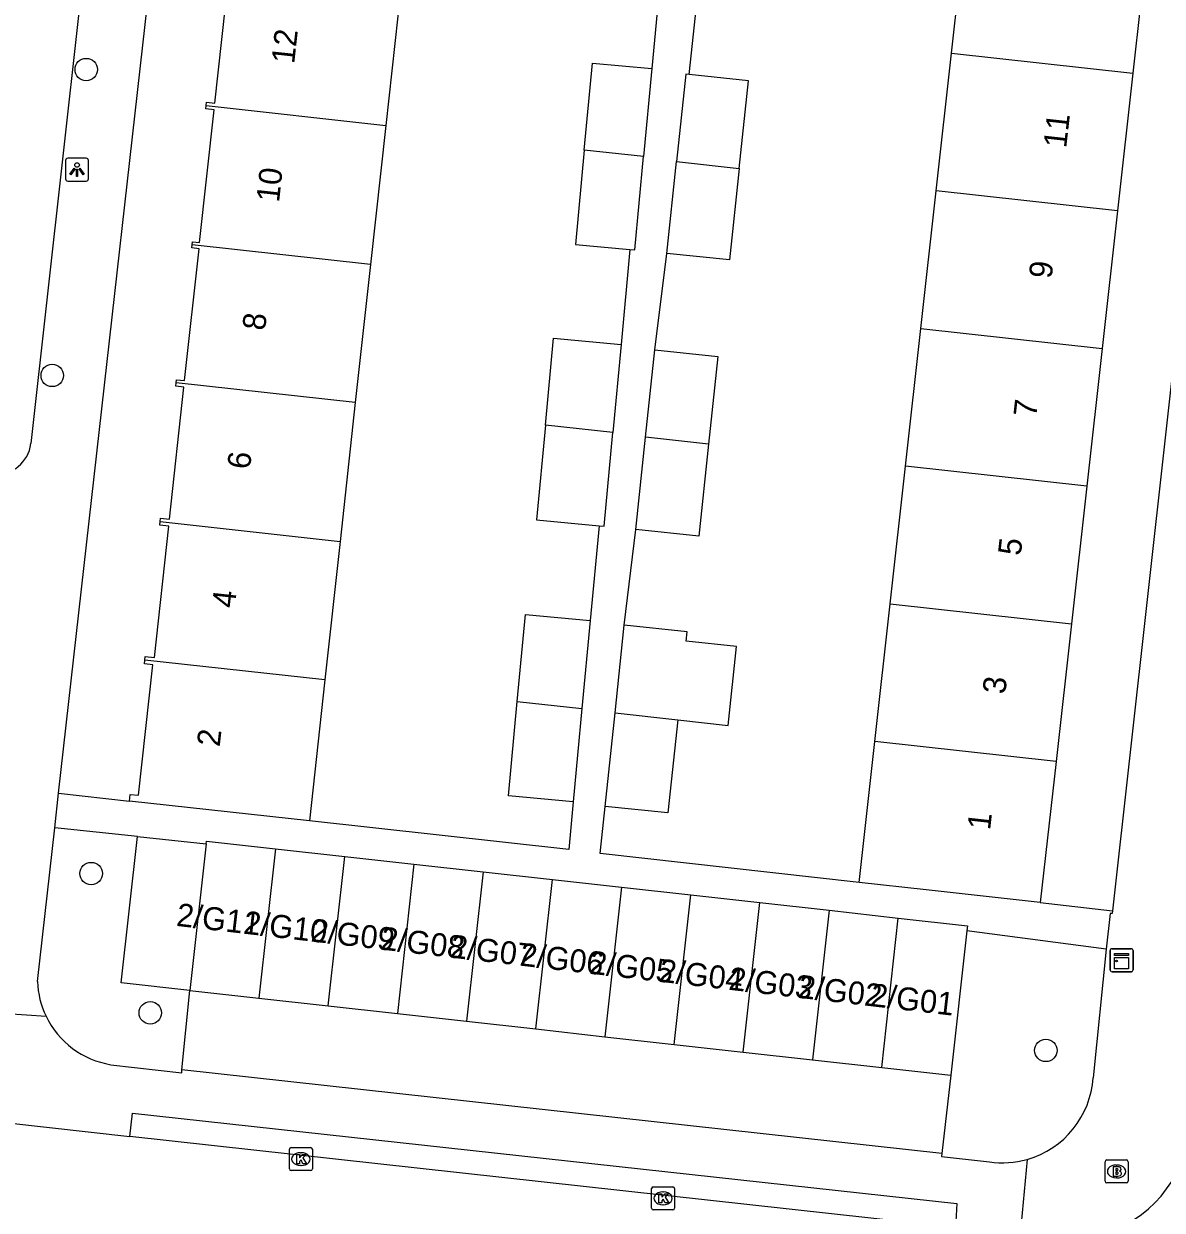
# Model space of a CAD drawing. Extents: x 161928 to 163055, y 386475 to 387428.
# Drawn here: x 162121.6 to 162171.2, y 386544.6 to 386596.2 of the extents above; entities that cross this region are included whole.
import ezdxf

# ---------------------------------------------------------------- set-up
doc = ezdxf.new("R2010")
doc.units = 0
for name, color, linetype in [('IMGEO_Boom', 7, 'Continuous'), ('IMGEO_Brandkraan', 7, 'Continuous'), ('IMGEO_Groenvoorziening', 7, 'Continuous'), ('IMGEO_Kast', 7, 'Continuous'), ('IMGEO_Kolk', 7, 'Continuous'), ('IMGEO_Lichtpunt', 7, 'Continuous'), ('IMGEO_Pand', 7, 'Continuous'), ('IMGEO_Pand_nummerreeks', 7, 'Continuous'), ('IMGEO_Rijbaan_lokaal_open', 7, 'Continuous'), ('IMGEO_Voetpad_gesloten', 7, 'Continuous'), ('IMGEO_Voetpad_open', 7, 'Continuous')]:
    doc.layers.add(name, color=color, linetype=linetype)

msp = doc.modelspace()

# ---------------------------------------------------------------- linework, layer by layer
at = {"layer": 'IMGEO_Boom'}
for centre in [(162124.314, 386594.21), (162122.834, 386580.895), (162124.531, 386559.208), (162127.103, 386553.146), (162166.086, 386551.512)]:
    msp.add_circle(centre, 0.489, dxfattribs=at)
at = {"layer": 'IMGEO_Brandkraan'}
for p, q in [((162168.666, 386545.815), (162168.666, 386546.667)), ((162168.741, 386546.741), (162169.593, 386546.741)), ((162169.154, 386546.521), (162169.179, 386546.521)), ((162169.667, 386546.667), (162169.667, 386545.815)), ((162169.177, 386545.961), (162169.152, 386545.961)), ((162169.593, 386545.741), (162168.741, 386545.741))]:
    msp.add_line(p, q, dxfattribs=at)
for points in [[(162168.666, 386545.815), (162168.666, 386546.667)], [(162168.741, 386546.741), (162169.593, 386546.741)], [(162169.014, 386546.441), (162169.014, 386546.041), (162169.227, 386546.041)], [(162169.245, 386546.441), (162169.014, 386546.441)], [(162169.193, 386546.36), (162169.139, 386546.36), (162169.139, 386546.284)], [(162169.139, 386546.284), (162169.192, 386546.284)], [(162169.667, 386546.667), (162169.667, 386545.815)], [(162169.201, 386546.208), (162169.139, 386546.208), (162169.139, 386546.127)], [(162169.139, 386546.127), (162169.201, 386546.127)], [(162169.593, 386545.741), (162168.741, 386545.741)]]:
    msp.add_lwpolyline(points, dxfattribs=at)
for centre, radius, start, end in [((162168.743, 386546.665), 0.0765, 91.552, 178.448), ((162168.743, 386546.665), 0.0765, 91.552, 178.448), ((162169.194, 386546.322), 0.0379, 267.8285, 90.9355), ((162169.249, 386546.296), 0.145, 59.4692, 91.5367), ((162169.274, 386546.343), 0.0922, 285.5137, 58.1501), ((162169.591, 386546.665), 0.0765, 1.552, 88.448), ((162169.591, 386546.665), 0.0765, 1.552, 88.448), ((162168.743, 386545.817), 0.0765, 181.552, 268.448), ((162168.743, 386545.817), 0.0765, 181.552, 268.448), ((162169.202, 386546.167), 0.0404, 269.8759, 90.5077), ((162169.233, 386546.292), 0.251, 268.6676, 293.5347), ((162169.279, 386546.151), 0.105, 301.3115, 78.989), ((162169.591, 386545.817), 0.0765, 271.552, 358.448), ((162169.591, 386545.817), 0.0765, 271.552, 358.448)]:
    msp.add_arc(centre, radius, start, end, dxfattribs=at)
for centre, major_axis, ratio, start_param, end_param in [((162169.153, 386546.241), (-0.387, 0.002), 0.722429, 4.712389, 7.853982), ((162169.178, 386546.241), (-0.39, 0.002), 0.717154, 1.570796, 4.712389)]:
    msp.add_ellipse(centre, major_axis=major_axis, ratio=ratio, start_param=start_param, end_param=end_param, dxfattribs=at)
at = {"layer": 'IMGEO_Groenvoorziening'}
msp.add_lwpolyline([(162128.822, 386554.12), (162125.84, 386554.452), (162126.549, 386560.818)], dxfattribs=at)
at = {"layer": 'IMGEO_Kast'}
for p, q in [((162168.886, 386555.013), (162168.886, 386555.854)), ((162168.886, 386555.854), (162168.886, 386555.013)), ((162168.961, 386555.938), (162169.802, 386555.938)), ((162169.802, 386555.938), (162168.961, 386555.938)), ((162169.886, 386555.863), (162169.886, 386555.022)), ((162169.886, 386555.022), (162169.886, 386555.863)), ((162169.811, 386554.938), (162168.97, 386554.938)), ((162168.97, 386554.938), (162169.811, 386554.938))]:
    msp.add_line(p, q, dxfattribs=at)
for points in [[(162169.081, 386555.728), (162169.681, 386555.728), (162169.681, 386555.643), (162169.081, 386555.643), (162169.081, 386555.728)], [(162169.081, 386555.553), (162169.681, 386555.553), (162169.681, 386555.064), (162169.081, 386555.064), (162169.081, 386555.553)]]:
    msp.add_lwpolyline(points, dxfattribs=at)
msp.add_circle((162169.165, 386555.402), 0.0377, dxfattribs=at)
for centre, start, end in [((162168.964, 386555.86), 92.4484, 184.2845), ((162168.964, 386555.86), 92.4484, 184.2845), ((162169.808, 386555.86), 2.4484, 94.2845), ((162169.808, 386555.86), 2.4484, 94.2845), ((162168.964, 386555.016), 182.4484, 274.2845), ((162168.964, 386555.016), 182.4484, 274.2845), ((162169.808, 386555.016), 272.4484, 4.2845), ((162169.808, 386555.016), 272.4484, 4.2845)]:
    msp.add_arc(centre, 0.0779, start, end, dxfattribs=at)
at = {"layer": 'IMGEO_Kolk'}
for p, q in [((162133.156, 386546.353), (162133.156, 386547.205)), ((162133.231, 386547.279), (162134.083, 386547.279)), ((162133.644, 386547.059), (162133.669, 386547.059)), ((162134.157, 386547.205), (162134.157, 386546.353)), ((162134.083, 386546.279), (162133.231, 386546.279)), ((162133.667, 386546.499), (162133.642, 386546.499)), ((162148.924, 386544.644), (162148.924, 386545.496)), ((162148.999, 386545.57), (162149.851, 386545.57)), ((162149.412, 386545.35), (162149.437, 386545.35)), ((162149.925, 386545.496), (162149.925, 386544.644)), ((162149.435, 386544.79), (162149.41, 386544.79)), ((162149.851, 386544.57), (162148.999, 386544.57))]:
    msp.add_line(p, q, dxfattribs=at)
for points in [[(162133.156, 386546.353), (162133.156, 386547.205)], [(162133.231, 386547.279), (162134.083, 386547.279)], [(162133.477, 386546.979), (162133.6, 386546.979), (162133.6, 386546.828), (162133.73, 386546.979), (162133.894, 386546.979), (162133.748, 386546.828), (162133.901, 386546.579), (162133.749, 386546.579), (162133.664, 386546.743), (162133.6, 386546.676), (162133.6, 386546.579), (162133.477, 386546.579), (162133.477, 386546.979)], [(162134.157, 386547.205), (162134.157, 386546.353)], [(162134.083, 386546.279), (162133.231, 386546.279)], [(162148.924, 386544.644), (162148.924, 386545.496)], [(162148.999, 386545.57), (162149.851, 386545.57)], [(162149.245, 386545.27), (162149.368, 386545.27), (162149.368, 386545.119), (162149.498, 386545.27), (162149.662, 386545.27), (162149.516, 386545.119), (162149.669, 386544.87), (162149.517, 386544.87), (162149.432, 386545.034), (162149.368, 386544.967), (162149.368, 386544.87), (162149.245, 386544.87), (162149.245, 386545.27)], [(162149.925, 386545.496), (162149.925, 386544.644)], [(162149.851, 386544.57), (162148.999, 386544.57)]]:
    msp.add_lwpolyline(points, dxfattribs=at)
for centre, start, end in [((162133.233, 386547.203), 91.552, 178.448), ((162133.233, 386547.203), 91.552, 178.448), ((162134.081, 386547.203), 1.552, 88.448), ((162134.081, 386547.203), 1.552, 88.448), ((162133.233, 386546.355), 181.552, 268.448), ((162133.233, 386546.355), 181.552, 268.448), ((162134.081, 386546.355), 271.552, 358.448), ((162134.081, 386546.355), 271.552, 358.448), ((162149.001, 386545.494), 91.552, 178.448), ((162149.001, 386545.494), 91.552, 178.448), ((162149.849, 386545.494), 1.552, 88.448), ((162149.849, 386545.494), 1.552, 88.448), ((162149.001, 386544.646), 181.552, 268.448), ((162149.001, 386544.646), 181.552, 268.448), ((162149.849, 386544.646), 271.552, 358.448), ((162149.849, 386544.646), 271.552, 358.448)]:
    msp.add_arc(centre, 0.0765, start, end, dxfattribs=at)
for centre, major_axis, ratio, start_param, end_param in [((162133.643, 386546.779), (-0.387, 0.002), 0.722429, 4.712389, 7.853982), ((162133.668, 386546.779), (-0.39, 0.002), 0.717154, 1.570796, 4.712389), ((162149.411, 386545.07), (-0.387, 0.002), 0.722429, 4.712389, 7.853982), ((162149.436, 386545.07), (-0.39, 0.002), 0.717154, 1.570796, 4.712389)]:
    msp.add_ellipse(centre, major_axis=major_axis, ratio=ratio, start_param=start_param, end_param=end_param, dxfattribs=at)
at = {"layer": 'IMGEO_Lichtpunt'}
for p, q in [((162123.415, 386590.258), (162123.415, 386589.451)), ((162123.415, 386590.258), (162123.415, 386589.451)), ((162124.317, 386590.353), (162123.509, 386590.353)), ((162124.317, 386590.353), (162123.509, 386590.353)), ((162124.411, 386589.451), (162124.411, 386590.258)), ((162124.411, 386589.451), (162124.411, 386590.258)), ((162123.509, 386589.357), (162124.317, 386589.357)), ((162123.509, 386589.357), (162124.317, 386589.357))]:
    msp.add_line(p, q, dxfattribs=at)
for points in [[(162123.789, 386589.922), (162123.828, 386589.894), (162123.64, 386589.632), (162123.602, 386589.659), (162123.789, 386589.922)], [(162123.891, 386589.874), (162123.938, 386589.874), (162123.938, 386589.552), (162123.891, 386589.552), (162123.891, 386589.874)], [(162124.001, 386589.894), (162124.039, 386589.921), (162124.226, 386589.659), (162124.187, 386589.631), (162124.001, 386589.894)]]:
    msp.add_lwpolyline(points, dxfattribs=at)
msp.add_circle((162123.914, 386590.056), 0.0994, dxfattribs=at)
for centre, start, end in [((162123.509, 386590.258), 90, 180), ((162123.509, 386590.258), 90, 180), ((162124.317, 386590.258), 0, 90), ((162124.317, 386590.258), 0, 90), ((162123.509, 386589.451), 180, 270), ((162123.509, 386589.451), 180, 270), ((162124.317, 386589.451), 270, 0), ((162124.317, 386589.451), 270, 360)]:
    msp.add_arc(centre, 0.0946, start, end, dxfattribs=at)
at = {"layer": 'IMGEO_Pand'}
for points in [[(162161.984, 386594.927), (162162.653, 386600.92)], [(162170.545, 386600.04), (162169.876, 386594.047)], [(162129.534, 386592.64), (162129.55, 386592.784), (162129.918, 386592.744), (162130.542, 386598.439), (162130.194, 386598.477), (162130.208, 386598.602)], [(162138.002, 386597.745), (162137.349, 386591.781)], [(162161.315, 386588.934), (162161.984, 386594.927)], [(162161.984, 386594.927), (162169.876, 386594.047)], [(162145.991, 386590.704), (162146.346, 386594.494), (162148.936, 386594.251)], [(162148.936, 386594.251), (162148.577, 386590.42)], [(162150.564, 386593.998), (162150.411, 386594.014), (162150.009, 386590.204)], [(162152.744, 386589.898), (162153.148, 386593.725), (162150.564, 386593.998)], [(162169.876, 386594.047), (162169.207, 386588.054)], [(162128.923, 386586.578), (162128.937, 386586.711), (162129.251, 386586.676), (162129.884, 386592.457), (162129.519, 386592.497), (162129.534, 386592.64)], [(162129.534, 386592.64), (162137.349, 386591.781)], [(162137.349, 386591.781), (162136.686, 386585.724)], [(162145.991, 386590.704), (162145.607, 386586.601), (162147.982, 386586.379)], [(162148.577, 386590.42), (162145.991, 386590.704)], [(162147.982, 386586.379), (162148.197, 386586.359), (162148.577, 386590.42)], [(162149.587, 386586.21), (162150.009, 386590.204)], [(162150.009, 386590.204), (162152.744, 386589.898)], [(162152.744, 386589.898), (162152.324, 386585.921), (162149.587, 386586.21)], [(162160.646, 386582.942), (162161.315, 386588.934)], [(162169.207, 386588.054), (162161.315, 386588.934)], [(162169.207, 386588.054), (162168.539, 386582.062)], [(162128.229, 386580.57), (162128.244, 386580.71), (162128.597, 386580.671), (162129.225, 386586.409), (162128.908, 386586.444), (162128.923, 386586.578)], [(162136.686, 386585.724), (162128.923, 386586.578)], [(162136.686, 386585.724), (162136.028, 386579.713)], [(162144.305, 386578.728), (162144.659, 386582.512), (162147.595, 386582.237)], [(162159.977, 386576.949), (162160.646, 386582.942)], [(162160.646, 386582.942), (162168.539, 386582.062)], [(162147.595, 386582.237), (162147.236, 386578.406)], [(162148.662, 386578.206), (162149.064, 386582.016)], [(162149.064, 386582.016), (162151.809, 386581.726), (162151.405, 386577.9)], [(162168.539, 386582.062), (162167.87, 386576.069)], [(162127.529, 386574.53), (162127.546, 386574.684), (162127.94, 386574.641), (162128.569, 386580.391), (162128.214, 386580.43), (162128.229, 386580.57)], [(162136.028, 386579.713), (162128.229, 386580.57)], [(162136.028, 386579.713), (162135.366, 386573.668)], [(162144.305, 386578.728), (162143.919, 386574.608), (162146.64, 386574.353)], [(162147.236, 386578.406), (162144.305, 386578.728)], [(162146.64, 386574.353), (162146.855, 386574.333), (162147.236, 386578.406)], [(162148.237, 386574.182), (162148.662, 386578.206)], [(162151.405, 386577.9), (162150.982, 386573.892), (162148.237, 386574.182)], [(162151.405, 386577.9), (162148.662, 386578.206)], [(162159.308, 386570.956), (162159.977, 386576.949)], [(162167.87, 386576.069), (162159.977, 386576.949)], [(162167.87, 386576.069), (162167.201, 386570.076)], [(162126.869, 386568.498), (162126.886, 386568.653), (162127.286, 386568.609), (162127.913, 386574.329), (162127.512, 386574.373), (162127.529, 386574.53)], [(162127.529, 386574.53), (162135.366, 386573.668)], [(162135.366, 386573.668), (162134.705, 386567.636)], [(162158.64, 386564.963), (162159.308, 386570.956)], [(162159.308, 386570.956), (162167.201, 386570.076)], [(162143.078, 386566.702), (162143.432, 386570.488), (162146.253, 386570.224)], [(162146.253, 386570.224), (162145.894, 386566.393)], [(162167.201, 386570.076), (162166.532, 386564.083)], [(162147.334, 386566.206), (162147.736, 386570.016)], [(162150.064, 386565.901), (162152.255, 386565.656), (162152.617, 386569.092), (162150.425, 386569.323), (162150.468, 386569.728), (162147.736, 386570.016)], [(162126.191, 386562.357), (162126.224, 386562.657), (162126.595, 386562.617), (162127.217, 386568.303), (162126.852, 386568.342), (162126.869, 386568.498)], [(162134.705, 386567.636), (162126.869, 386568.498)], [(162134.705, 386567.636), (162134.034, 386561.498)], [(162145.514, 386562.333), (162142.693, 386562.598), (162143.078, 386566.702)], [(162143.078, 386566.702), (162145.894, 386566.393)], [(162145.894, 386566.393), (162145.514, 386562.333)], [(162146.904, 386562.136), (162147.334, 386566.206)], [(162150.064, 386565.901), (162149.636, 386561.847), (162146.904, 386562.136)], [(162147.334, 386566.206), (162150.064, 386565.901)], [(162157.955, 386558.825), (162158.64, 386564.963)], [(162166.532, 386564.083), (162158.64, 386564.963)], [(162166.532, 386564.083), (162165.847, 386557.945)], [(162134.034, 386561.498), (162126.191, 386562.357)], [(162129.532, 386560.504), (162128.822, 386554.12)], [(162129.532, 386560.504), (162129.546, 386560.626), (162132.558, 386560.291)], [(162132.558, 386560.291), (162131.834, 386553.785)], [(162132.558, 386560.291), (162135.57, 386559.955)], [(162134.846, 386553.449), (162135.57, 386559.955)], [(162135.57, 386559.955), (162138.582, 386559.62)], [(162138.582, 386559.62), (162137.858, 386553.114)], [(162138.582, 386559.62), (162141.594, 386559.285)], [(162141.594, 386559.285), (162140.87, 386552.779)], [(162141.594, 386559.285), (162144.606, 386558.95)], [(162143.882, 386552.444), (162144.606, 386558.95)], [(162144.606, 386558.95), (162147.619, 386558.614)], [(162165.847, 386557.945), (162160.878, 386558.499), (162157.955, 386558.825)], [(162147.619, 386558.614), (162146.894, 386552.108)], [(162147.619, 386558.614), (162150.631, 386558.279)], [(162149.906, 386551.773), (162150.631, 386558.279)], [(162150.631, 386558.279), (162153.643, 386557.944)], [(162152.919, 386551.438), (162153.643, 386557.944)], [(162153.643, 386557.944), (162156.655, 386557.609)], [(162156.655, 386557.609), (162155.931, 386551.103)], [(162156.655, 386557.609), (162159.667, 386557.273)], [(162158.943, 386550.767), (162159.667, 386557.273)], [(162159.667, 386557.273), (162162.679, 386556.938), (162162.655, 386556.72)], [(162162.655, 386556.72), (162161.955, 386550.432)], [(162128.822, 386554.12), (162131.834, 386553.785)], [(162131.834, 386553.785), (162134.846, 386553.449)], [(162134.846, 386553.449), (162137.858, 386553.114)], [(162137.858, 386553.114), (162140.87, 386552.779)], [(162140.87, 386552.779), (162143.882, 386552.444)], [(162143.882, 386552.444), (162146.894, 386552.108)], [(162146.894, 386552.108), (162149.906, 386551.773)], [(162149.906, 386551.773), (162152.919, 386551.438)], [(162152.919, 386551.438), (162155.931, 386551.103)], [(162155.931, 386551.103), (162158.943, 386550.767)], [(162158.943, 386550.767), (162161.955, 386550.432)]]:
    msp.add_lwpolyline(points, dxfattribs=at)
at = {"layer": 'IMGEO_Rijbaan_lokaal_open'}
for points in [[(162119.074, 386548.556), (162126.209, 386547.768)], [(162162.151, 386543.798), (162126.209, 386547.768)]]:
    msp.add_lwpolyline(points, dxfattribs=at)
msp.add_arc((162167.093, 386548.602), 5.278, 264.3517, 332.3721, dxfattribs=at)
at = {"layer": 'IMGEO_Voetpad_gesloten'}
msp.add_lwpolyline([(162126.209, 386547.768), (162126.323, 386548.776), (162162.213, 386544.84), (162162.151, 386543.798)], dxfattribs=at)
at = {"layer": 'IMGEO_Voetpad_open'}
for points in [[(162123.113, 386562.703), (162128.549, 386610.991)], [(162125.366, 386609.092), (162121.902, 386577.926)], [(162174.366, 386605.829), (162168.995, 386557.594)], [(162149.329, 386598.439), (162148.936, 386594.251)], [(162150.564, 386593.998), (162151.008, 386598.203)], [(162147.982, 386586.379), (162147.595, 386582.237)], [(162149.064, 386582.016), (162149.587, 386586.21)], [(162146.64, 386574.353), (162146.253, 386570.224)], [(162147.736, 386570.016), (162148.237, 386574.182)], [(162122.944, 386561.198), (162123.113, 386562.703)], [(162123.113, 386562.703), (162126.191, 386562.357)], [(162145.514, 386562.333), (162145.32, 386560.264), (162134.034, 386561.498)], [(162157.955, 386558.825), (162146.687, 386560.082), (162146.904, 386562.136)], [(162122.19, 386554.504), (162122.944, 386561.198)], [(162126.549, 386560.818), (162122.944, 386561.198)], [(162126.549, 386560.818), (162129.532, 386560.504)], [(162165.847, 386557.945), (162168.995, 386557.594)], [(162168.995, 386557.594), (162168.981, 386557.465), (162168.883, 386557.469), (162168.714, 386555.921)], [(162168.714, 386555.921), (162162.655, 386556.72)], [(162168.714, 386555.921), (162168.149, 386550.32)], [(162128.48, 386550.667), (162128.822, 386554.12)], [(162119.137, 386553.235), (162122.565, 386552.998)], [(162125.384, 386550.889), (162128.471, 386550.538), (162128.48, 386550.667)], [(162161.56, 386547.02), (162128.48, 386550.667)], [(162161.955, 386550.432), (162161.56, 386547.02)], [(162161.56, 386547.02), (162161.545, 386546.887), (162163.632, 386546.654)], [(162165.28, 386546.768), (162164.968, 386543.507)]]:
    msp.add_lwpolyline(points, dxfattribs=at)
for centre, radius, start, end in [((162120.423, 386578.091), 1.489, 264.041, 353.654), ((162126, 386554.653), 3.813, 182.2405, 205.7246), ((162126.004, 386554.656), 3.817, 205.7371, 260.6599), ((162164.19, 386550.583), 3.968, 285.9443, 356.1991), ((162164.189, 386550.57), 3.955, 261.9031, 286.0112)]:
    msp.add_arc(centre, radius, start, end, dxfattribs=at)

# ---------------------------------------------------------------- texts
at = {"layer": 'IMGEO_Pand_nummerreeks'}
for s, rotation, p in [('12', 83.7749, (162133.366, 386594.437)), ('11', 83.6319, (162166.974, 386590.768)), ('10', 83.7749, (162132.707, 386588.405)), ('9', 83.6319, (162166.34, 386585.082)), ('8', 83.7749, (162132.098, 386582.825)), ('7', 83.6319, (162165.667, 386579.053)), ('6', 83.7749, (162131.44, 386576.783)), ('5', 83.6319, (162164.994, 386573.023)), ('4', 83.7749, (162130.781, 386570.744)), ('3', 83.6319, (162164.321, 386566.994)), ('2', 83.7749, (162130.122, 386564.704)), ('1', 83.6319, (162163.661, 386561.078)), ('2/G11', 353.4045, (162128.205, 386556.935)), ('2/G10', 353.4045, (162131.129, 386556.597)), ('2/G09', 353.4045, (162134.063, 386556.257)), ('2/G08', 353.4045, (162137.099, 386555.906)), ('2/G07', 353.4045, (162140.126, 386555.556)), ('2/G06', 353.4045, (162143.157, 386555.206)), ('2/G05', 353.4045, (162146.187, 386554.856)), ('2/G04', 353.4045, (162149.217, 386554.505)), ('2/G03', 353.4045, (162152.248, 386554.155)), ('2/G02', 353.4045, (162155.272, 386553.805)), ('2/G01', 353.4045, (162158.418, 386553.441))]:
    msp.add_text(s, height=1, rotation=rotation, dxfattribs=at).set_placement(p)

doc.saveas('drawing.dxf')
